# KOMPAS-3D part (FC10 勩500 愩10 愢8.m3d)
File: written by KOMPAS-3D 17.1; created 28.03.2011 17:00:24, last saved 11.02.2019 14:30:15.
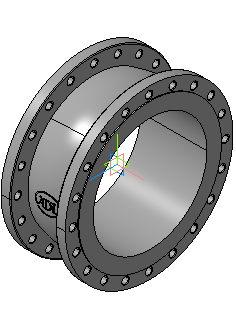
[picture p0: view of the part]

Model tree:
1. Плоскость XY
2. Плоскость ZX
3. Плоскость ZY
4. Ось X
5. Ось Y
6. Ось Z
7. Начало координат
8. Операция без истории:2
